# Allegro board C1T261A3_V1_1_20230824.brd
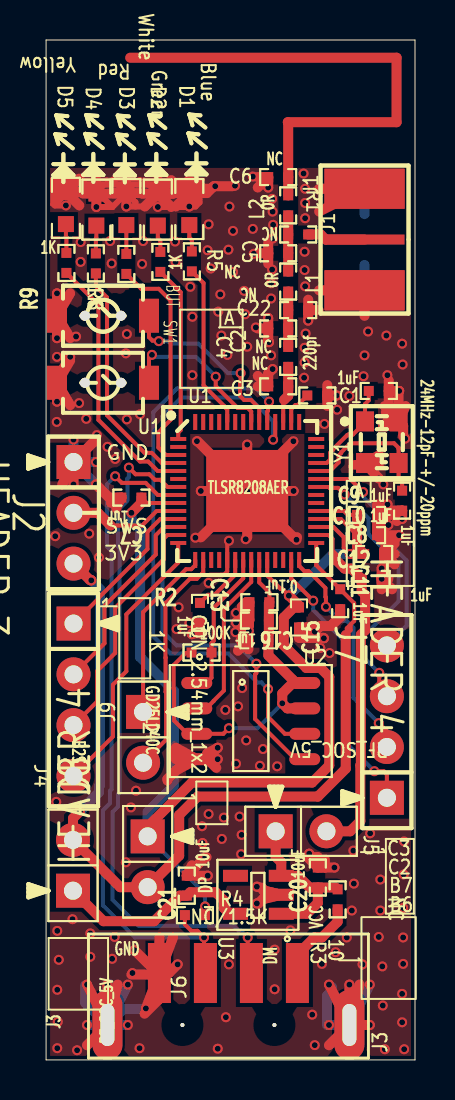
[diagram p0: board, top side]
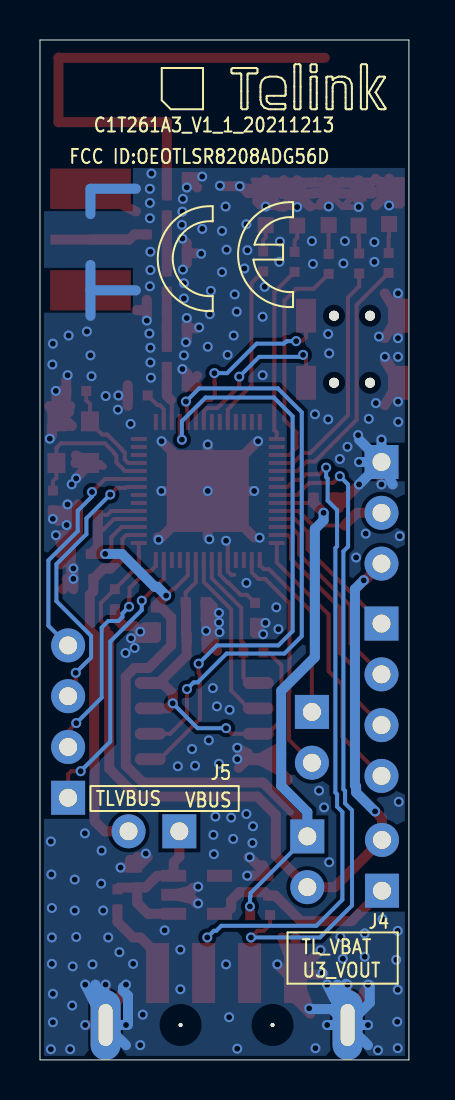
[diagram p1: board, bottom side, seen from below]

Outline 18.45 x 51 mm; copper layers: TOP, BOTTOM. Coordinates in mm from the lower left corner of the outline.
Outline path: 0,51 18.45,51 18.45,0 0,0 0,51

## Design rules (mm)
constraint set DEFAULT: 

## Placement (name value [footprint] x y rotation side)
C1  1uF  [0402]  13.56 33.22 180 top
C2  220pf  [0402]  12.11 35.15 90 top
C3  NC  [0402]  11.61 33.68 0 top
C4  1pF  [0402]  11.61 36.58 0 top
C5  2.4pF  [0402]  11.61 40.34 0 top
C6  1nH  [0402]  11.61 44.15 0 top
C7  1uF  [0402]  4.27 28.12 180 top
C8  1uF  [0402]  16.41 25.3 0 top
C9  1uF  [0402]  16.05 27.25 0 top
C10  1uF  [0402]  16.05 26.24 0 top
C11  1uF  [0402]  14.71 23.04 270 top
C12  1uF  [0402]  16.28 24.05 0 top
C13  1uF  [0402]  7.7 22.35 270 top
C14  1uF  [0402]  12.65 22.12 270 top
C15  NC  [0402]  10.67 22.89 180 top
C16  NC  [0402]  10.64 21.97 180 top
C17  NC  [0402]  10.62 20.98 180 top
C18  NC  [0402]  16.64 33.45 180 top
C19  NC  [0402]  17.81 27.97 90 top
C20  10uF  [0402]  13.59 9.12 90 top
C21  10uF  [0402]  7.04 8.71 90 top
C22  NC  [0402]  12.61 37.49 180 top
D1  Blue  [0603-LED]  7.16 42.55 90 top
D2  Green  [0603-LED]  5.59 42.52 90 top
D3  White  [0603-LED]  4.01 42.55 90 top
D4  Red  [0603-LED]  2.51 42.52 90 top
D5  Yellow  [0603-LED]  0.99 42.6 90 top
J1  RFIN  [SMA-H]  15.93 41.02 0 top
J2  HEADER 3  [HDR254M-1X3]  1.37 29.9 270 top
J3  USB_SMT_4PIN  [USB-M-4]  9.12 4.34 90 top
J4  B2S  [HDR254F-1X2X850]  1.35 11 270 top
J5  RF_SOC_5V  [HDR254F-1X2X850]  14.02 11.43 180 top
J6  RF_SOC_5V  [HDR254F-1X2X850]  5.08 8.64 90 top
J7  HEADER 4  [HDR254F-1X4X850]  17.04 20.73 270 top
J8  HEADER 4  [HDR254F-1X4X850]  1.37 14.2 90 top
J9  CON_2.54mm_1x2  [HDR254F-1X2X850]  4.85 14.86 90 top
L1  2.4nH  [0402]  12.11 38.92 90 top
L2  1.8pF  [0402]  12.11 42.73 90 top
R1  NC  [0402]  12.61 41.27 180 top
R2  100K  [0402]  7.77 20.37 0 top
R3  10  [0402]  14.58 8.03 90 top
R4  NC/1.5K  [0402]  7.44 7.24 180 top
R5  1K  [0402]  7.29 39.93 90 top
R6  1K  [0402]  5.71 39.9 90 top
R7  1K  [0402]  4.01 39.8 90 top
R8  1K  [0402]  2.49 39.83 90 top
R9  1K  [0402]  1.02 39.85 90 top
SW1  BUT  [BUTSMD2PX4_00Y3_00]  2.84 37.21 270 top
SW2  BUT  [BUTSMD2PX4_00Y3_00]  2.84 33.86 270 top
U1  TLSR8208AER  [QFN_7X7_56PIN_0P4_4P10X4P10]  10.06 28.45 0 top
U2  P25Q40SU-SSH-I  [W25X10_20_40BL]  10.24 16.94 270 top
U3  XC6219_3.3V_SOT-23-5  [SOT-23-5]  10.62 8.26 90 top
Y1  24MHz-12pF-+/-20ppm  [OSCCC200X250X080]  16.79 30.89 0 top

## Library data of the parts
C1 C7-C17 = C1005X5R1C105K
C2 = C1005X5R1C104K
C3-C6 C22 = C1608_NC
C18 C19 = C1005_NC
C20 C21 = C1608X5R0J106M
D1-D4 = 0603D_Green
D5 = 0603D_Red
J1 = SMA_JACK_2
J2 = HEADER 3: User Part Number: pn; Tolerance: RichardLC
J3 = USB_SMT_1
J4 = B2S_0: User Part Number: pn; Tolerance: RichardLC
J5 J6 = B2S_3: User Part Number: pn; Tolerance: RichardLC
J7 J8 = HEADER_4: User Part Number: pn; Tolerance: RichardLC
J9 = CON_2.54mm_1x2: User Part Number: pn; Tolerance: RichardLC
L1 L2 = MLK1608_000R
R1 R9 = RS0402K332JT
R2 = RS0603K102JT
R3 R4 = RS0402K100JT
R5-R8 = RS0402K102JT
SW1 SW2 = SW PUSHBUTTON-SPST/SM
U1 = TLSR8208AER_3: Tolerance: RichardLC
U2 = GD25LD40C: Tolerance: RichardLC
U3 = XC6219_1.3V_SOT-23-5
Y1 = OSC_25x32_4pin

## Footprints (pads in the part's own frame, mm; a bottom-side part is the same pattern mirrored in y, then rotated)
0402
  rect 0.5x0.5 smd: 1(-0.5,0) 2(0.5,0)
0603-LED
  rect 0.8x0.8 smd: A(-0.8,0) C(0.8,0)
BUTSMD2PX4_00Y3_00
  round 0.5 hole 0.7 unplated: (0,0.9) (0,-0.9)
  rect 1.7x1 smd: 1(0,2.3) 2(0,-2.3)
HDR254F-1X2X850
  rect 1.7x1.7 hole 0.9: 1(2.54,0)
  round 1.7 hole 0.9: 2(0,0)
HDR254F-1X4X850
  rect 1.7x1.7 hole 0.9: 1(7.62,0)
  round 1.7 hole 0.9: 2(5.08,0) 3(2.54,0) 4(0,0)
HDR254M-1X3
  rect 1.7x1.7 hole 0.9: 1(0,0)
  round 1.7 hole 0.9: 2(2.54,0) 3(5.08,0)
OSCCC200X250X080
  rect 0.9x1 smd: 1(-0.84,1.04) 2(-0.84,-1.04) 3(0.84,-1.04) 4(0.84,1.04)
QFN_7X7_56PIN_0P4_4P10X4P10
  rect 0.8x0.2 smd: 1(-3.45,2.6) 2(-3.45,2.2) 3(-3.45,1.8) 4(-3.45,1.4) 5(-3.45,1) 6(-3.45,0.6) 7(-3.45,0.2) 8(-3.45,-0.2) 9(-3.45,-0.6) 10(-3.45,-1) 11(-3.45,-1.4) 12(-3.45,-1.8) 13(-3.45,-2.2) 14(-3.45,-2.6) 29(3.45,-2.6) 30(3.45,-2.2) 31(3.45,-1.8) 32(3.45,-1.4) 33(3.45,-1) 34(3.45,-0.6) 35(3.45,-0.2) 36(3.45,0.2) 37(3.45,0.6) 38(3.45,1) 39(3.45,1.4) 40(3.45,1.8) 41(3.45,2.2) 42(3.45,2.6)
  rect 0.2x0.8 smd: 15(-2.6,-3.45) 16(-2.2,-3.45) 17(-1.8,-3.45) 18(-1.4,-3.45) 19(-1,-3.45) 20(-0.6,-3.45) 21(-0.2,-3.45) 22(0.2,-3.45) 23(0.6,-3.45) 24(1,-3.45) 25(1.4,-3.45) 26(1.8,-3.45) 27(2.2,-3.45) 28(2.6,-3.45) 43(2.6,3.45) 44(2.2,3.45) 45(1.8,3.45) 46(1.4,3.45) 47(1,3.45) 48(0.6,3.45) 49(0.2,3.45) 50(-0.2,3.45) 51(-0.6,3.45) 52(-1,3.45) 53(-1.4,3.45) 54(-1.8,3.45) 55(-2.2,3.45) 56(-2.6,3.45)
  rect 4.1x4.1 smd: 57(0,0)
SMA-H
  rect 4x0.5 smd: 1(0,0)
  rect 4x2 smd: 2(0,-2.54) 3(0,2.54) 4(0,-2.54) 5(0,2.54)
SOT-23-5
  rect 0.6x1.25 smd: 1(-0.95,-1.145) 2(0,-1.145) 3(0.95,-1.145) 4(0.95,1.145) 5(-0.95,1.145)
USB-M-4
  round 0.2 hole 1.7 unplated: (-2.6,2.3) (-2.6,-2.3)
  rect 3x1.15 smd: 1(0,-3.45) 2(0,-1.15) 3(0,1.15) 4(0,3.45)
  oval 3.5x1.5 hole 2.1x0.7: S1(-2.6,6.05) S2(-2.6,-6.05)
W25X10_20_40BL
  oval 0.6x1.55 smd: 1(-1.905,-2.7) 2(-0.635,-2.7) 3(0.635,-2.7) 4(1.905,-2.7) 5(1.905,2.7) 6(0.635,2.7) 7(-0.635,2.7) 8(-1.905,2.7)

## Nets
GND: C1.1 C3.1 C4.1 C5.1 C6.1 C7.2 C8.2 C9.2 C10.2 C11.2 C12.2 C13.2 C14.2 C15.2 C16.2 C17.2 C18.1 C19.1 C20.2 C21.2 C22.1 D1.C(CATHODE) D2.C(CATHODE) D3.C(CATHODE) D4.C(CATHODE) D5.C(CATHODE) J1.2 J1.3 J1.4 J1.5 J2.1 J3.4 J3.S1 J3.S2 SW1.2 SW2.2 U1.19 U1.57 U2.4 U3.2(VSS) Y1.2 Y1.4
VBUS: C20.1 J5.1 R3.2 U3.1 U3.3
TL_A4: J8.1 U1.11
TL_A5: J8.2 U1.12
TL_A6: J8.3 U1.13
TL_A7: J8.4 U1.14
TL_ANT: C2.1 C3.2 U1.45
TL_AVDD3: C7.1 C8.1 C9.1 C10.1 C14.1 J6.1 R4.1 U1.9 U1.24 U1.31 U1.32 U1.33
TL_B0: J9.1 U1.15
TL_B1: J9.2 U1.16
TL_B6: J7.1 U1.27
TL_B7: J7.2 U1.28
TL_C2: J7.3 U1.36
TL_C3: J7.4 U1.37
TL_D2: R5.1 U1.52
TL_D3: R6.1 U1.1
TL_D5: R7.1 U1.3
TL_D6: R8.1 U1.4
TL_D7: R9.1 U1.5
TL_DM_A1: J3.2 U1.7
TL_DP_A2: J3.3 R4.2 U1.8
TL_E0_MSDO: U1.46 U2.5
TL_E1_MCLK: U1.47 U2.6
TL_E2_MSCN: R2.2 U1.21 U2.1
TL_E3_MSDI: U1.22 U2.2
TL_F0_KEY1: SW1.1 U1.48
TL_F1_KEY2: SW2.1 U1.49
TL_RST: C1.2 U1.44
TL_SWS_A3: J2.2 U1.10
TL_VBAT: C11.1 J2.3 J4.2 J6.2 U1.29
TL_VBUS: C12.1 J5.2 U1.30
TL_VDDF: C15.1 C16.1 C17.1 R2.1 U1.23 U2.3(W\P\) U2.7 U2.8
TL_XC1: C18.2 U1.39 Y1.1
TL_XC2: C19.2 U1.38(XC2) Y1.3
N19730495: C13.1 U1.20
N19767303: C21.1 J4.1 U3.5
N19767305: J3.1 R3.1
N19771186: C2.2 C4.2 C22.2 L1.1
N19771236: C6.2 L2.2
N19771246: C5.2 L1.2 L2.1 R1.2
N19784595: J1.1 R1.1
N197530131: D4.A R8.2
N197530210: D1.A R5.2
N197530291: D2.A R6.2
N197530370: D3.A R7.2
N197661920: D5.A R9.2

Pads without a net: U1 2 6 17 18 25 26 34 35 40 41 42 43 50 51 53 54 55 56; U3 4

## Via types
v1: diameter 0.5, hole 0.3, TOP to BOTTOM, 238 vias

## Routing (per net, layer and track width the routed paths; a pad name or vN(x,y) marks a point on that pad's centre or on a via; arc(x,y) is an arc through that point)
GND: length 250.2
  TOP w0.2: 8.74,24.26 8.89,24.26 9.06,24.43 U1.19 9.06,25.87 v1(9.14,25.96) ; 14.71,22.23 14.51,22.03 14.36,22.03 14.07,21.74 13.77,21.74 13.72,21.69 ; 1.66,44.04 1.66,43.99 0.48,43.99 ; 1.66,44.04 1.66,44.07 1.77,44.07 1.82,44.02 ; 1.66,44.04 0.3,44.04 0.3,42.77 0.48,42.77 ; 4.89,44.02 5.14,43.76 ; 4.89,44.02 4.68,44.02 4.7,44.03 4.68,44.04 4.66,44.02 3.35,44.02 3.33,44.04 ; 4.89,44.02 6.26,44.02 ; 3.03,44.02 3.28,44.02 3.33,44.07 3.33,44.04 ; 3.03,44.02 3.03,43.84 D4.C ; 3.03,44.02 1.82,44.02 ; 1.82,44.02 2.44,43.4 ; v1(2.49,28.78) 2.49,28.78 ; 6.26,44.02 7.83,44.02 ; 6.26,44.02 6.26,43.99 6.9,43.34 ; 3.59,43.76 3.33,44.03 3.33,44.04 ; v1(16.1,36.42) 16.1,36.35 ; v1(7.29,21.29) 7.29,21.45 C13.2
  TOP w0.3: Y1.2 15.44,29.85 15.27,29.67 15.77,29.67 ; 0.48,43.9 D5.C 0.62,43.4 0.48,43.26 ; 0.48,43.9 0.48,43.26 ; 0.48,43.9 0.48,43.99 ; 0.48,43.9 1.28,43.9 1.39,43.8 ; v1(4.01,42.67) 4.47,42.67 ; 4.47,42.67 4.47,42.89 D3.C 3.59,43.76 ; 4.47,42.67 4.94,42.67 ; v1(5.59,42.65) 6.15,42.65 ; 6.15,42.65 5.88,42.91 ; 6.15,42.65 7.14,42.65 v1(7.16,42.67) ; 0.99,43.31 0.44,42.75 0.44,42.73 v1(0.99,42.73) ; 6.03,43.76 5.14,43.76 ; 5.14,43.76 3.59,43.76 ; 5.14,43.76 D2.C ; v1(7.16,42.67) 7.47,42.67 7.67,42.88 7.67,43.03 7.59,43.11 ; v1(7.16,42.67) 7.59,43.11 ; 0.48,43.26 0.48,42.77 ; 1.83,43.76 3.59,43.76 ; 5.88,42.91 6.29,43.32 ; 5.88,42.91 5.59,43.21 ; 7.59,43.34 7.59,43.11 ; v1(2.51,42.65) 3.32,42.65 ; 3.32,42.65 2.65,43.32 ; 3.32,42.65 3.99,43.32 ; D1.C 6.85,43.66 ; 6.85,43.66 8.43,43.66 v1(8.46,43.69) ; 6.85,43.66 6.35,43.66 ; 6.17,43.9 7.72,43.9 ; 17.12,23.67 17.12,24.05
  TOP w0.5: 17.22,25.3 C8.2 ; 17.22,25.3 17.43,25.3 ; 17.22,25.3 17.22,24.89 ; C8.2 17.43,24.78 ; C8.2 16.91,24.18 v1(16.78,24.05) ; C8.2 17.43,25.82 ; C8.2 16.91,25.49 v1(17.65,26.24) C10.2 ; C9.2 17.59,27.25 C19.1 ; C9.2 v1(17.07,27.77) ; C9.2 C10.2 ; C9.2 17.07,26.73 ; C9.2 16.55,27.77 ; v1(10.06,28.45) v1(12.38,28.45) ; v1(10.06,28.45) 10.06,26.13 ; v1(10.06,28.45) 12.37,26.14 12.55,26.14 ; v1(10.06,28.45) 10.06,28.63 ; v1(10.06,28.45) 7.74,26.13 ; v1(10.06,28.45) 7.57,30.94 ; v1(10.06,28.45) v1(7.74,28.45) ; 1.66,44.07 1.39,43.8 ; v1(2.49,28.78) 3.15,28.12 C7.2 ; 0.81,28.78 J2.1 ; J2.1 v1(1.37,28.78) ; J2.1 2.49,31.02 ; C14.2 12.65,21.1 13.06,21.1 ; C14.2 13.06,21.62 ; C14.2 13.17,21.1 ; Y1.2 15.77,29.67 ; Y1.2 v1(16.64,29.08) ; Y1.2 16.66,30.23 ; Y1.2 16.67,29.85 ; J3.4 6.35,6.11 ; J3.4 5.56,4.34 v1(4.42,5.49) ; J3.4 v1(4.99,2.57) ; J3.4 5.67,3.05 4.93,2.31 ; J3.4 5.67,6.11 ; J3.4 6.15,4.34 v1(6.58,4.78) ; J3.4 5.59,4.27 4.27,4.27 ; 13.06,21.1 13.06,21.62 ; 13.06,21.1 13.87,21.1 v1(13.89,21.08) ; C7.2 3.51,27.6 ; C7.2 3.25,27.86 ; C16.2 9.8,21.97 ; C16.2 9.62,21.45 ; C16.2 10.17,22 C15.2 10.02,22.89 9.8,22.66 9.8,21.97 ; C16.2 10.14,21.71 9.88,21.45 ; C16.2 9.62,21.71 ; 9.8,21.97 9.6,21.97 v1(9.5,21.87) ; 13.06,21.62 13.23,21.62 v1(13.44,21.41) 13.72,21.69 14.25,21.69 14.71,22.15 C11.2 ; 1.84,43.32 D4.C ; D4.C 2.51,43.99 ; D4.C v1(2.51,42.65) ; D4.C 2.44,43.4 D5.C ; D4.C 3.99,43.32 D3.C ; C20.2 13.94,9.62 ; C20.2 13.07,10.14 ; C20.2 13.59,10.14 13.16,10.14 v1(13.16,10.31) ; 13.94,9.62 13.94,10.01 ; 13.94,9.62 v1(14.42,9.62) ; SW1.2 1.2,38.33 ; SW1.2 1.2,36.09 ; SW1.2 v1(0.54,36.09) ; SW1.2 v1(0.54,38.33) ; D1.C 8.04,43.34 8.38,43.69 v1(8.46,43.69) 9.32,43.69 ; D1.C 6.49,42.67 ; D1.C 7.16,44.02 ; D1.C 6.39,43.34 6.37,43.32 D2.C ; D1.C v1(7.16,42.67) ; U2.4 8.08,15.04 ; U2.4 6.49,14.47 ; U2.4 6.49,15.61 ; U2.4 7.06,15.04 ; 8.08,15.04 v1(8.58,15.04) ; 8.08,15.04 8.51,14.61 ; D5.C 0.99,44.07 ; D5.C 0.99,43.31 ; D5.C 1.66,42.73 ; v1(16.78,24.05) 17.3,23.53 ; v1(16.78,24.05) 17.12,24.05 ; v1(16.78,24.05) 16.78,23.53 ; v1(16.78,24.05) v1(16.78,24.57) ; D3.C 3.34,43.34 ; D3.C 4.79,43.34 4.82,43.32 D2.C ; D3.C 4.01,44.02 ; D3.C v1(4.01,42.67) ; 10.87,8.47 U3.2 ; U3.2 10.88,8.47 10.8,8.6 v1(10.54,8.66) ; U3.2 11.05,8.26 10.62,7.82 v1(10.54,7.82) ; U3.2 10.87,8.04 ; 15.93,37.21 J1.2 13.66,38.48 ; 6.38,15.34 6.68,15.04 ; 6.68,15.04 7.06,15.04 ; 6.68,15.04 6.49,15.04 ; Y1.4 17.98,32.7 ; Y1.4 16.94,32.7 ; Y1.4 17.09,31.93 16.87,31.7 17.4,31.7 Y1.4 ; Y1.4 17.86,31.7 17.86,31.19 ; Y1.4 17.63,32.51 ; 5.59,43.21 D2.C ; D2.C 5.59,43.99 ; D2.C 4.94,42.67 ; D2.C 6.26,42.65 ; v1(11.33,34.54) 11.11,34.32 C3.1 ; 16.99,32.38 17.22,32.61 17.63,32.61 ; 17.63,32.61 17.63,33.42 v1(17.66,33.45) C18.1 ; 17.63,32.61 17.63,32.51 ; 17.7,32.59 17.63,32.51 ; J3.S2 v1(16.19,1.74) ; J3.S2 v1(14.15,3.76) ; J3.S2 15.68,3.76 ; J3.S2 14.15,0.73 ; J3.S2 v1(15.17,3.76) ; 17.29,27.47 C19.1 ; C19.1 v1(17.81,27.05) ; C19.1 17.55,26.95 ; 17.14,32.93 C18.1 ; C18.1 17.14,33.97 ; C21.2 v1(7.96,10.13) 8.03,10.13 ; C21.2 7.3,9.73 ; C21.2 v1(8.09,9.21) ; 14.06,32.7 C1.1 ; C1.1 v1(14.53,33.22) ; C1.1 14.06,33.74 ; 10.59,43.62 C6.1 ; C6.1 v1(11.11,43.62) ; C6.1 10.59,44.15 ; v1(13.11,36.97) C22.1 ; C22.1 13.11,38.01 ; C22.1 13.63,37.49 ; 6.03,43.76 6.26,43.99 ; C10.2 17.07,25.72 ; C10.2 17.07,26.76 ; 7.06,15.04 6.07,14.05 6.07,13.97 ; C17.2 9.73,20.98 ; C17.2 10.12,20.53 ; C17.2 9.6,20.46 ; C17.2 9.6,21.5 ; C5.1 11.11,40.86 ; C5.1 10.59,40.34 ; C5.1 11.11,39.81 ; v1(10.06,30.77) 10.06,28.63 ; 10.06,28.63 12.32,30.89 ; SW2.2 0.54,34.04 v1(1.2,35.16) ; SW2.2 v1(0.54,32.92) ; SW2.2 1.2,32.74 ; SW2.2 1.2,34.98 ; J3.S1 3.58,3.76 ; J3.S1 v1(2.05,3.76) ; J3.S1 2.05,0.73 ; J3.S1 v1(3.07,3.76) ; v1(7.29,21.29) 7.34,21.33 7.7,21.33 C13.2 ; C13.2 7.44,21.33 ; C13.2 v1(7.18,21.85) ; C4.1 v1(11.11,37.1) ; C4.1 10.59,36.58 ; C4.1 11.11,35.93 v1(11.15,35.89) ; 10.59,34.2 C3.1 ; C3.1 10.59,33.68 ; 13.66,42.43 J1.3 13.66,43.56 ; 8.3,15.32 v1(8.58,15.61) 8.06,15.32 8.3,15.32
  BOTTOM w0.5: v1(14.15,1.74) J3.S2 ; J3.S2 15.24,1.81 15.24,3.58 ; J3.S2 15.68,3.76 ; J3.S2 14.15,0.73 ; J3.S2 v1(16.19,3.76) ; 1.96,3.73 1.96,2.86 J3.S1 ; 3.15,1.82 J3.S1 ; 3.15,1.82 3.15,3.81 ; 3.15,1.82 3.87,2.54 4.95,2.54 ; J3.S1 3.58,3.76 ; J3.S1 2.05,0.73 ; J3.S1 v1(4.09,1.74) ; J3.S1 v1(2.05,1.74) ; J3.S1 v1(4.09,3.76) ; J2.1 v1(1.37,31.02) ; J2.1 v1(2.49,29.9) ; J2.1 2.49,31.02 ; J2.1 v1(2.49,28.78) ; J2.1 0.81,28.78 ; 14.3,3.63 14.3,3.46 14.05,3.21 14.05,1.74 ; 15.93,37.21 J1.2 ; J1.2 15.93,39.75 ; J1.2 13.66,38.48 ; 13.66,43.56 J1.3 15.93,42.29
  vias: v1(0.54,35.16) v1(0.53,31.9) v1(0.46,26.19) v1(0.51,12.9) v1(0.56,6.45) v1(0.64,5) v1(0.56,3.51) v1(0.58,1.91) v1(0.56,0.58) v1(1.32,7.04) v1(1.5,36.17) v1(1.55,0.48) v1(1.73,40.89) v1(1.73,39.9) v1(1.65,32.84) v1(2.01,32.05) v1(2.16,26.31) v1(2.21,6.32) v1(2.21,5.16) v1(2.54,31.24) v1(2.64,25.12) v1(3.07,30.66) v1(3.2,40.94) v1(3.28,39.83) v1(3.3,5.05) v1(3.43,6.15) v1(3.45,30.05) v1(4.04,36.3) v1(3.99,35.33) v1(4.04,32.03) v1(3.99,9.88) v1(4.24,12.62) v1(4.32,4.34) v1(4.5,13.46) v1(4.7,32.28) v1(4.67,0.58) v1(4.8,39.8) v1(4.85,40.94) v1(6.45,40.92) v1(6.48,39.9) v1(6.53,21.54) v1(6.63,22.63) v1(7.21,38.66) v1(7.32,37.16) v1(7.32,34.24) v1(7.54,30.94) v1(7.47,26.11) v1(7.8,11.68) v1(7.82,10.85) v1(8.13,41.78) v1(8.08,40.49) v1(8.13,23.85) v1(8.13,12.29) v1(8.23,39.57) v1(8.61,37.41) v1(8.59,0.56) v1(8.71,38.28) v1(8.76,36.22) v1(8.79,11.05) v1(8.89,12.12) v1(8.97,17.5) v1(8.99,2.13) v1(9.12,40.51) v1(9.07,35.26) v1(9.14,4.78) v1(9.17,42.67) v1(9.35,41.45) v1(9.35,39.4) v1(9.45,43.71) v1(9.5,22.35) v1(9.47,21.39) v1(9.5,14.81) v1(9.6,17.68) v1(9.68,12.17) v1(9.8,18.59) v1(9.78,11.25) v1(9.75,10.29) v1(9.91,38.46) v1(9.96,37.29) v1(9.98,26.04) v1(10.01,15.98) v1(10.06,35.66) v1(10.14,21.45) v1(10.34,44.17) v1(10.34,41.55) v1(10.39,40.31) v1(10.49,36.63) v1(10.69,14.71) v1(10.85,15.54) v1(11.3,43.05) v1(11.33,42.42) v1(11.33,41.07) v1(11.3,39.52) v1(11.25,38.84) v1(11.25,38.07) v1(11.25,35.23) v1(11.35,41.76) v1(11.43,5.51) v1(11.43,3.53) v1(11.56,14.68) v1(12.22,6.48) v1(12.37,30.94) v1(12.52,26.01) v1(12.88,44.32) v1(12.93,40.41) v1(12.93,39.5) v1(12.93,35.61) v1(12.93,34.87) v1(12.9,34.11) v1(12.95,43.56) v1(12.95,42.85) v1(12.95,42.09) v1(12.95,38.68) v1(12.98,36.32) v1(13.31,2.26) v1(13.44,0.74) v1(13.72,20.6) v1(13.79,4.8) v1(13.92,31.8) v1(14.17,20.35) v1(14.48,5.38) v1(14.55,32.51) v1(15.04,6.12) v1(15.16,33.2) v1(15.29,7.47) v1(15.37,10.46) v1(15.39,8.81) v1(15.82,4.78) v1(15.93,35.23) v1(15.88,34.19) v1(16.21,11.33) v1(16.64,6.15) v1(16.71,9.02) v1(16.71,7.47) v1(16.81,4.67) v1(16.84,2.72) v1(16.87,28.78) v1(16.94,0.53) v1(17.02,36.22) v1(17.07,34.24) v1(17.12,26.75) v1(17.81,35.81) v1(17.83,34.77) v1(17.81,3.3) v1(17.81,1.88) v1(17.91,10.92) v1(17.88,9.27) v1(17.86,7.59) v1(17.86,6.12) v1(17.86,4.8) v1(17.91,0.53) v1(17.96,31.06)
VBUS: length 8.3
  TOP w0.2: 14.49,8.62 R3.2
  TOP w0.5: C20.1 14.49,8.62 ; C20.1 13.17,8.62 12.59,9.21 U3.3 11.76,9.88 11.48,10.16 J5.1 ; C20.1 13.59,7.85 13.05,7.3 11.76,7.3
TL_A4: length 7.9
  TOP w0.2: J8.1 2.62,23.06 2.62,23.09 5.07,25.54 5.07,26.4 5.71,27.05 U1.11
TL_A5: length 10
  TOP w0.2: J8.2 2.92,20.83 2.92,22.71 5.49,25.27 5.49,26.24 5.9,26.65 U1.12
TL_A6: length 12
  TOP w0.2: U1.13 6.07,26.25 5.89,26.07 5.89,25.04 3.45,22.61 3.45,20.35 2.55,19.44 2.55,17.92 J8.3
TL_A7: length 13.8
  TOP w0.2: U1.14 6.61,24.87 4.01,22.28 4.01,19.43 3.34,18.76 3.34,16.17 J8.4
TL_ANT: length 2.9
  TOP w0.2: 11.9,33 11.86,32.96 U1.45
  TOP w0.5: 11.9,33 12.11,33.21 C3.2 C2.1
TL_AVDD3: length 63.1
  TOP w0.2: R4.1 7.94,7.66 v1(7.95,7.67) ; C7.1 5.04,27.85 U1.9 ; C10.1 14.74,27.05 U1.32 ; U1.24 11.06,24.22 11.73,23.55 11.81,23.55 v1(12.14,23.22) ; U1.33 14.89,27.45 15.08,27.25 C9.1 ; U1.31 14.37,26.65 14.88,26.14 14.88,25.6 v1(15.19,25.3)
  TOP w0.5: C9.1 C10.1 15.55,25.65 C8.1 v1(15.19,25.3) ; v1(4.27,27.36) 4.77,27.86 C7.1 ; v1(12.14,23.22) 12.15,23.22 12.65,22.72 C14.1 12.39,22.62 11.89,22.12 11.89,20.73 13.02,19.6 13.72,19.6 14.16,19.16 14.16,14.73 13.3,13.87 7.29,13.87 5.08,11.66 J6.1
  BOTTOM w0.2: v1(7.95,7.67) 7.95,8.14 7.92,8.17 7.92,8.33 J6.1
  BOTTOM w0.5: v1(15.19,25.3) 14.35,25.3 12.71,23.65 12.58,23.65 v1(12.14,23.22) ; J6.1 5.08,12.4 6.39,13.7 6.39,18.45 4.71,20.14 4.71,26.54 4.27,26.98 v1(4.27,27.36)
TL_B0: length 8.8
  TOP w0.2: U1.15 7.46,24.74 7.26,24.54 7,24.54 4.85,22.39 J9.1
TL_B1: length 11.6
  TOP w0.2: U1.16 7.86,24.38 7.53,24.05 7.19,24.05 5.97,22.83 5.97,20.12 5.98,20.11 5.98,18.4 6,18.37 6,16.42 5.99,16.42 5.99,16 J9.2
TL_B6: length 14.1
  TOP w0.2: v1(16.42,14.44) 16.89,14.44 17.04,14.28 J7.1 ; v1(13.36,22.96) 12.26,24.06 U1.27
  BOTTOM w0.2: v1(13.36,22.96) 13.36,22.49 14.94,20.92 14.94,15.92 v1(16.42,14.44)
TL_B7: length 11.6
  TOP w0.2: v1(16.64,16.84) 17.04,16.43 J7.2 ; v1(14,22.66) 14,23.13 13.97,23.15 13.97,23.6 13.12,24.44 12.91,24.44 12.66,24.7 U1.28
  BOTTOM w0.2: v1(16.64,16.84) 15.37,18.11 15.37,21.62 15.04,21.95 14.53,21.95 14.33,22.15 14.33,22.32 v1(14,22.66)
TL_C2: length 14
  TOP w0.2: 17.02,18.17 J7.3 17.04,18.54 16.66,18.92 v1(16.66,19.35) ; U1.36 14.13,28.65 14.17,28.6 14.6,28.6 v1(14.94,28.27)
  BOTTOM w0.2: v1(14.94,28.27) 16.13,27.08 16.13,26.29 17.63,24.79 17.63,22.94 15.89,21.2 15.89,20.12 v1(16.66,19.35)
TL_C3: length 11.6
  TOP w0.2: v1(15.85,28.4) 15.2,29.05 U1.37
  BOTTOM w0.2: J7.4 18.03,21.71 18.03,24.97 16.56,26.44 16.56,27.46 15.85,28.17 v1(15.85,28.4)
TL_D2: length 8.3
  TOP w0.2: R5.1 7.87,38.84 7.87,33.73 8.92,32.69 8.92,32.66 9.06,32.52 U1.52
TL_D3: length 8.8
  TOP w0.2: U1.1 6.61,31.37 6.73,31.49 6.73,38.39 R6.1
TL_D5: length 11.5
  TOP w0.2: U1.3 5.99,30.25 5.62,30.62 5.62,31.37 5.82,31.57 5.82,31.6 6.22,32 6.22,37.97 5.64,38.56 4.76,38.56 R7.1
TL_D6: length 11.9
  TOP w0.2: R8.1 2.49,38.68 3.05,38.13 3.05,32.23 4.93,30.35 5.28,30.35 5.79,29.85 U1.4
TL_D7: length 13.1
  TOP w0.2: R9.1 2.62,37.75 2.62,32 4.7,29.92 5.11,29.92 5.58,29.45 U1.5
TL_DM_A1: length 34.3
  TOP w0.2: U1.7 6.07,28.65 5.71,29.01 5.44,29.01 5.16,29.28 4.47,29.28 v1(4.14,29.62) ; v1(10.08,6.12) 10.08,4.53 J3.2
  BOTTOM w0.2: v1(4.14,29.62) 4.14,29.15 4.06,29.07 4.06,27.97 3.59,27.49 3.59,25.68 3.68,25.6 3.68,13.37 3.59,13.28 3.59,12.66 3.33,12.4 3.33,8 4.63,6.71 9.38,6.71 9.64,6.45 9.75,6.45 v1(10.08,6.12)
TL_DP_A2: length 34.7
  TOP w0.2: J3.3 7.9,4.41 v1(7.9,6.12) 7.57,6.45 7.26,6.45 6.94,6.77 R4.2 ; U1.8 5.58,28.25 4.98,28.85 3.79,28.85 v1(3.45,29.18)
  BOTTOM w0.2: v1(7.9,6.12) 4.45,6.12 2.84,7.72 2.84,12.48 3.19,12.83 3.19,13.45 3.28,13.53 3.28,25.43 3.04,25.67 3.04,28.77 v1(3.45,29.18)
TL_E0_MSDO: length 30.6
  TOP w0.2: U1.46 11.46,31.12 v1(11.35,31.01) ; v1(10.52,19.81) 10.52,19.34 10.45,19.28 10.45,17.04 12.46,15.04 U2.5 13.01,15.04
  BOTTOM w0.2: v1(10.52,19.81) 9.6,20.73 6.53,20.73 5.82,21.44 5.82,32.18 6.76,33.12 10.17,33.12 11.35,31.94 v1(11.35,31.01)
TL_E1_MCLK: length 29.2
  TOP w0.2: U1.47 11.06,32.42 11.1,32.46 11.1,32.87 v1(11.15,32.92) ; U2.6 11.94,16.31 11.1,17.15 v1(11.1,18.54)
  BOTTOM w0.2: v1(11.15,32.92) 10.49,33.58 6.55,33.58 5.36,32.38 5.36,21.18 6.22,20.32 9.12,20.32 10.56,18.87 10.77,18.87 v1(11.1,18.54)
TL_E2_MSCN: length 7.4
  TOP w0.2: U2.1 8.01,18.85 8.27,19.11 R2.2 8.27,20.84 8.38,20.95 8.38,22.61 9.86,24.08 U1.21
TL_E3_MSDI: length 8.9
  TOP w0.2: U1.22 10.26,23.9 8.89,22.53 8.89,18.47 8.38,17.95 8.38,17.94 8.01,17.58 U2.2 7.52,17.58 7.5,17.59
TL_F0_KEY1: length 9.5
  TOP w0.2: SW1.1 5.14,36.14 5.32,35.97 5.56,35.97 5.59,35.94 v1(5.64,35.94) ; v1(9.73,34.34) 9.73,33.87 9.7,33.85 9.7,33.2 9.9,33 10.25,33 10.66,32.59 U1.48
  BOTTOM w0.2: v1(5.64,35.94) 6.11,35.94 6.16,35.89 6.18,35.89 6.26,35.81 7.62,35.81 9.09,34.34 v1(9.73,34.34)
TL_F1_KEY2: length 8.4
  TOP w0.2: U1.49 10.26,32.42 10.08,32.6 9.58,32.6 8.48,33.69 v1(8.48,34.16) ; SW2.1 5.14,35.11 v1(5.29,35.26)
  BOTTOM w0.2: v1(8.48,34.16) 7.49,35.15 5.4,35.15 v1(5.29,35.26)
TL_RST: length 1.7
  TOP w0.2: U1.44 12.26,32.54 12.46,32.74 12.58,32.74 C1.2
TL_SWS_A3: length 5.8
  TOP w0.2: 3.23,26.72 4.8,26.72 5.53,27.45 U1.10
  TOP w0.5: J2.2 2.59,27.36 3.23,26.72
TL_VBAT: length 46.1
  TOP w0.2: 15.04,21.26 15.04,21.58 15.23,21.78 ; 14.99,21.25 15.23,21.49 15.23,21.78 ; 15.23,21.78 15.41,21.95 15.41,22.84 C11.1 13.51,24.74 U1.29
  TOP w0.5: J2.3 2.18,24 2.24,24 2.26,23.98 v1(2.26,23.98) ; 14.99,21.25 14.99,14.56 13.59,13.17 7.58,13.17 6.65,12.24 6.65,10.21 J6.2 3.71,8.64 J4.2 1.35,12.08 v1(1.69,12.43)
  BOTTOM w0.5: v1(1.69,12.43) 2.64,13.38 2.64,13.68 2.7,13.73 2.7,23.54 v1(2.26,23.98)
TL_VBUS: length 17.9
  TOP w0.2: U1.30 14.13,26.25 14.33,26.05 14.33,25.32
  TOP w0.4: 14.33,25.32 14.49,25.16 14.49,25.01
  TOP w0.5: 14.49,25.01 14.93,24.57 15.27,24.57 C12.1 15.78,23.43 15.96,23.26 15.96,21.48 15.74,21.27 15.74,14.75 15.72,14.73 15.72,11.94 15.21,11.43 J5.2
TL_VDDF: length 20.2
  TOP w0.2: v1(9.14,16.59) 8.86,16.31 U2.3 7.06,16.31 6.4,16.97 6.4,18.54 6.38,18.57 6.38,19.74 6.99,20.35 7.25,20.35 R2.1 ; C15.1 11.17,23.37 10.66,23.88 U1.23
  TOP w0.5: 12.34,18.85 U2.8 ; 12.34,18.85 12.34,19.01 11.12,20.23 C17.1 11.12,21.33 11.14,21.35 C16.1 11.14,22.86 C15.1 ; 12.34,18.85 11.81,18.32 v1(11.81,17.83) 12.06,17.58 U2.7
  BOTTOM w0.2: v1(11.81,17.83) 10.57,16.59 v1(9.14,16.59)
TL_XC1: length 5.2
  TOP w0.2: C18.2 16.14,32.98 15.95,32.79 Y1.1 15.95,31.88 15.34,31.27 15.12,31.27 15.08,31.24 15.05,31.24 14.36,30.54 14.36,30.51 14.21,30.36 14.21,30.02 14.03,29.85 U1.39
TL_XC2: length 7.2
  TOP w0.2: U1.38 14.2,29.45 14.63,29.88 14.63,30.22 14.76,30.35 14.76,30.38 15.21,30.84 17.4,30.84 17.63,30.61 17.63,30.57 17.63,30.57 Y1.3 17.63,29.11 17.81,28.94 C19.2
N19730495: length 3.1
  TOP w0.2: C13.1 8.1,23.26 8.42,23.26 9.02,23.86 9.06,23.86 9.46,24.26 U1.20
N19767303: length 10
  TOP w0.5: J4.1 2.87,6.93 5.4,6.93 6.68,8.21 C21.1 7.21,8.38 8.48,8.38 8.89,7.98 8.89,7.59 9.18,7.3 9.47,7.3
N19767305: length 4.2
  TOP w0.5: J3.1 12.57,5.27 13.42,6.12 13.79,6.12 14.58,6.91 R3.1
N19771186: length 2.8
  TOP w0.5: L1.1 C22.2 C4.2 C2.2
N19771236: length 25.6
  TOP w0.5: 4.21,50.11 17.53,50.11 17.53,46.89 12.09,46.89 12.11,46.87 C6.2 L2.2
N19771246: length 2.8
  TOP w0.5: L1.2 C5.2 R1.2 L2.1
N19784595: length 2.9
  TOP w0.5: R1.1 13.73,41.27 13.98,41.02 J1.1
N197530131: length 1.4
  TOP w0.2: R8.2 2.49,41.07 2.51,41.1 D4.A
N197530210: length 1.4
  TOP w0.2: 7.16,41.74 7.16,41.12 7.29,41 R5.2
N197530291: length 1.4
  TOP w0.2: D2.A 5.59,41.1 5.71,40.97 R6.2
N197530370: length 1.4
  TOP w0.2: R7.2 4.01,41.74
N197661920: length 1.5
  TOP w0.2: D5.A 0.99,41.18 1.02,41.15 R9.2

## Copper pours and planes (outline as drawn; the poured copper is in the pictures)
GND on TOP: 0.2,0.2 0.2,44.6 18.25,44.6 18.25,0.2 ; 21 cut-outs
GND on BOTTOM: 0.2,0.2 0.2,44.6 18.25,44.6 18.25,0.2 ; 16 cut-outs

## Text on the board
Ref Des/Silkscreen Bottom: J4 | U3_VOUT | TL_VBAT | J5 | VBUS | TLVBUS | C1T261A3_V1_1_20211213 | FCC ID:OEOTLSR8208ADG56D
Ref Des/Silkscreen Top: A | C3 | C2 | B7 | B6 | 3V3 | SWS | GND
User.6: FIGURE | SIZE | 0.3 | 0.9 | 0.7 | 1.7 | 2.1x0.7 | DRILL CHART: TOP to BOTTOM | ALL UNITS ARE IN MILLIMETERS | PLATED | NON-PLATED | QTY | 238 | 19 | 4 | 2
